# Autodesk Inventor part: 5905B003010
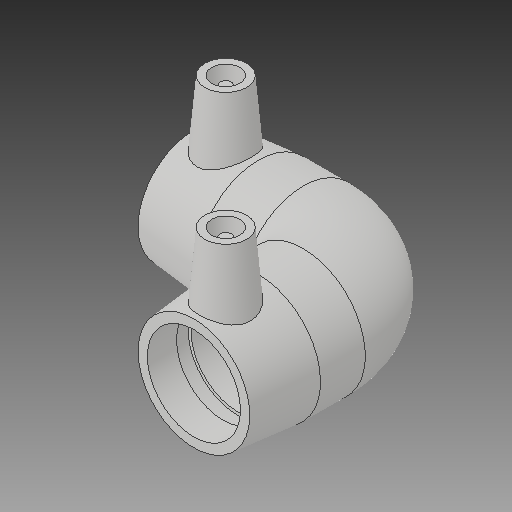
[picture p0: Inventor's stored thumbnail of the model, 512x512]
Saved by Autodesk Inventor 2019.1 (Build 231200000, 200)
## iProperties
Created: 2017-06
Part Number: 5905B003010
Material: Generic
Description: PLASSON 90° ELBOW ASTM 1''
Document SubType Name: Modeling
Designer: KIM
Mass: 55.0731 g
Surface Area: 148.067 cm^2
Volume: 55.0731 cm^3
Density: 1 g/cm^3
Appearance: Default
Author: KIM
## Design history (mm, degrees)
derived "5905B.ipt"
feature "Solid1::5905B.ipt"
tag "TaggingFeature1"
body "Solid1"
other parameters: "d_" = 33.3, "L_" = 78.486, "L_1" = 39.116, "D_" = 44.45, "A_" = 42.672, "d2" = 44.45, "d4" = 23.08412, "d5" = 40.005, "d8" = 168 deg, "d10" = 15.6464, "d11" = 5.21547, "d14" = 17.6296, "d18" = 33.3, "d19" = 3.52592, "d20" = 168 deg, "d22" = 40.894, "d23" = 44.45, "d24" = 39.66718, "d29" = 42.672, "d30" = 15, "d31" = 47.0916, "d34" = 5 deg, "d35" = 15, "d39" = 5 deg, "d41" = 4, "d42" = 14, "d43" = 0, "d45" = 4, "d46" = 14, "d47" = 0, "d49" = 33.3, "d50" = 28.305, "d51" = 15.6464, "d52" = 39.116, "d54" = 90 deg, "d65" = 33.3, "d67" = 45 deg, "d71" = 90 deg, "d75" = 2.2225, "d82" = 45 deg, "d83" = 39.116, "d84" = 40.005, "d86" = 20.0025, "d87" = 90 deg, "d90" = 39.116, "d91" = 0, "d92" = 39.116, "d93" = 0, "d94" = 90 deg, "d95" = 20.447, "d98" = 78.486, "d101" = 3, "d102" = 0, "d103" = 3, "d104" = 0, "d105" = 11.34364, "d106" = 2.83591, "d107" = 78.486, "d110" = 21.5138
